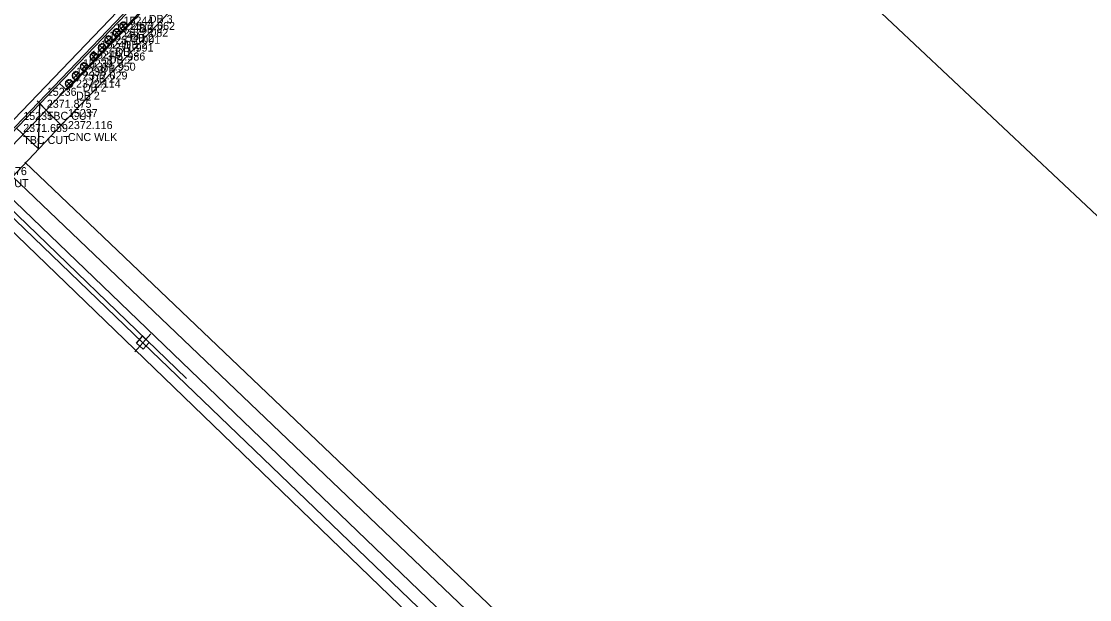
# Model space of a CAD drawing. Extents: x 2377639 to 2379738, y 729875 to 732734.
# Drawn here: x 2378522.8 to 2378789.8, y 730567.8 to 730712.2 of the extents above; entities that cross this region are included whole.
import ezdxf

# ---------------------------------------------------------------- set-up
doc = ezdxf.new("R2010")
doc.units = 0
for name, color, linetype in [('Default', 7, 'Continuous'), ('TOPO_CURBGTR_Back-of-Curb', 7, 'Continuous'), ('TOPO_CURBGTR_Face-of-Curb', 7, 'Continuous'), ('TOPO_CURBGTR_Lip-of-Gutter', 7, 'Continuous'), ('TOPO_DATA_Elevations', 7, 'Continuous'), ('TOPO_ELEC_Cable_Overhead-Exist', 7, 'Continuous'), ('TOPO_ELEC_Power-Pole', 7, 'Continuous'), ('TOPO_GAS_Line', 7, 'Continuous'), ('TOPO_LNDSCP_Tree', 7, 'Continuous'), ('TOPO_SAN_Plastic-Pipe', 7, 'Continuous'), ('TOPO_STORM_Line-Other', 7, 'Continuous'), ('TOPO_SW_Back', 7, 'Continuous'), ('TOPO_TELE_Overhead-Line', 7, 'Continuous'), ('TOPO_TV_Cable-Overhead', 7, 'Continuous'), ('TOPO_WTRUTIL_Line', 7, 'Continuous')]:
    doc.layers.add(name, color=color, linetype=linetype)

# ---------------------------------------------------------------- blocks, each defined once
blk = doc.blocks.new('DB_1')
at = {"layer": 'Default'}
for centre, radius, start, end in [((-0.101, -0.007), 0.0254, 74.3823, 292.6388), ((-0.092, 0.042), 0.0254, 45.5823, 263.8388), ((-0.059, 0.081), 0.0254, 16.7823, 235.0388), ((-0.012, 0.1), 0.0254, 347.9823, 206.2388), ((0, 0), 0.00318, 0, 180), ((0, 0), 0.00318, 180, 0), ((0.038, 0.093), 0.0254, 319.1823, 177.4388), ((0.079, 0.064), 0.0254, 290.3823, 148.6388), ((0.1, 0.018), 0.0254, 261.5823, 119.8388), ((-0.086, -0.056), 0.0254, 103.1823, 321.4388), ((-0.049, -0.09), 0.0254, 131.9823, 278.4601), ((-0.025, -0.1), 0.0254, 218.161, 4.6388), ((0.026, -0.1), 0.0254, 175.1823, 33.4388), ((0.07, -0.076), 0.0254, 203.9823, 62.2388), ((0.097, -0.033), 0.0254, 232.7823, 91.0388)]:
    blk.add_arc(centre, radius, start, end, dxfattribs=at)
blk = doc.blocks.new('UP_1')
at = {"layer": 'Default'}
for p, q in [((0, 0.0381), (0, -0.0381)), ((-0.0145, 0.0145), (0.0145, 0.0145)), ((-0.0145, -0.0145), (-0.0145, 0.0145)), ((0.0145, 0.0145), (0.0145, -0.0145)), ((0.0145, -0.0145), (-0.0145, -0.0145))]:
    blk.add_line(p, q, dxfattribs=at)

msp = doc.modelspace()

# ---------------------------------------------------------------- linework, layer by layer
at = {"layer": 'TOPO_CURBGTR_Back-of-Curb'}
msp.add_lwpolyline([(2378428.64, 730588.82), (2378465.5, 730627.29), (2378502.36, 730665.57), (2378506, 730669.31), (2378527.48, 730691.63), (2378605.98, 730773.58), (2378608.94, 730776.83)], dxfattribs=at)
at = {"layer": 'TOPO_CURBGTR_Face-of-Curb'}
msp.add_lwpolyline([(2378428.28, 730589.17), (2378465.14, 730627.64), (2378502, 730665.92), (2378505.64, 730669.66), (2378527.12, 730691.97), (2378605.61, 730773.92), (2378608.57, 730777.17)], dxfattribs=at)
at = {"layer": 'TOPO_CURBGTR_Lip-of-Gutter'}
msp.add_lwpolyline([(2378609, 730779.64), (2378604.75, 730775.02), (2378431.05, 730594.21), (2378426.07, 730588.91)], dxfattribs=at)
at = {"layer": 'TOPO_DATA_Elevations'}
for p, q in [((2378547.64, 730710.36), (2378549.06, 730711.78)), ((2378547.64, 730711.78), (2378549.06, 730710.36)), ((2378545.97, 730708.69), (2378547.38, 730710.11)), ((2378545.97, 730710.11), (2378547.38, 730708.69)), ((2378542.28, 730704.95), (2378543.7, 730706.37)), ((2378542.28, 730706.37), (2378543.7, 730704.95)), ((2378543.93, 730706.9), (2378545.35, 730708.31)), ((2378543.93, 730708.31), (2378545.35, 730706.9)), ((2378540.23, 730702.73), (2378541.64, 730704.15)), ((2378540.23, 730704.15), (2378541.64, 730702.73)), ((2378537.82, 730700.19), (2378539.23, 730701.61)), ((2378537.82, 730701.61), (2378539.23, 730700.19)), ((2378535.78, 730697.99), (2378537.2, 730699.41)), ((2378535.78, 730699.41), (2378537.2, 730697.99)), ((2378534.06, 730695.97), (2378535.48, 730697.38)), ((2378534.06, 730697.38), (2378535.48, 730695.97)), ((2378526.77, 730690.92), (2378528.19, 730692.34)), ((2378526.77, 730692.34), (2378528.19, 730690.92)), ((2378532.06, 730685.62), (2378533.47, 730687.03)), ((2378532.06, 730687.03), (2378533.47, 730685.62))]:
    msp.add_line(p, q, dxfattribs=at)
at = {"layer": 'TOPO_ELEC_Cable_Overhead-Exist'}
for p, q in [((2378553.19, 730631.94), (2378457.25, 730724.11)), ((2378651.85, 730537.16), (2378553.19, 730631.94))]:
    msp.add_line(p, q, dxfattribs=at)
at = {"layer": 'TOPO_GAS_Line'}
msp.add_line((2378523.71, 730677.02), (2378852.87, 730363.52), dxfattribs=at)
at = {"layer": 'TOPO_SAN_Plastic-Pipe'}
msp.add_line((2378737.85, 730466.14), (2378460.89, 730730.47), dxfattribs=at)
at = {"layer": 'TOPO_STORM_Line-Other'}
for q in [(2378187, 730332.08), (2378188.38, 730333.53)]:
    msp.add_line((2378608.31, 730773.03), q, dxfattribs=at)
at = {"layer": 'TOPO_SW_Back'}
msp.add_line((2378527.48, 730691.63), (2378532.77, 730686.32), dxfattribs=at)
for points in [[(2378532.38, 730696.74), (2378534.18, 730695.01), (2378607.54, 730771.6), (2378605.7, 730773.28)], [(2378474.98, 730627.55), (2378508.09, 730660.21), (2378532.77, 730686.32), (2378606.65, 730763.63), (2378611.23, 730768.23), (2378618.35, 730761.5)], [(2378521.63, 730685.55), (2378527.13, 730680.36), (2378527.48, 730691.63)]]:
    msp.add_lwpolyline(points, dxfattribs=at)
at = {"layer": 'TOPO_TELE_Overhead-Line'}
for p, q in [((2378751.05, 730446.34), (2378268.25, 730910.16)), ((2378564.13, 730622.97), (2378353.69, 730826.29))]:
    msp.add_line(p, q, dxfattribs=at)
at = {"layer": 'TOPO_TV_Cable-Overhead'}
msp.add_line((2378746.7, 730441.54), (2378265.21, 730906.27), dxfattribs=at)
at = {"layer": 'TOPO_WTRUTIL_Line'}
msp.add_line((2378650.11, 730796.86), (2378885.8, 730574.99), dxfattribs=at)

# ---------------------------------------------------------------- block references
at = {"layer": 'TOPO_ELEC_Power-Pole', "xscale": 78.74, "yscale": 78.74000000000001, "rotation": -41.90525780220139}
msp.add_blockref('UP_1', (2378553.19, 730631.94), dxfattribs=at)
at = {"layer": 'TOPO_LNDSCP_Tree', "xscale": 7.8740000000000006, "yscale": 7.8740000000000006}
for p in [(2378548.35, 730711.07), (2378546.68, 730709.4), (2378542.99, 730705.66), (2378544.64, 730707.61), (2378540.94, 730703.44), (2378538.52, 730700.9), (2378536.49, 730698.7), (2378534.77, 730696.67)]:
    msp.add_blockref('DB_1', p, dxfattribs=at)

# ---------------------------------------------------------------- texts
at = {"layer": 'TOPO_DATA_Elevations'}
for s, p in [('15243', (2378546.35, 730709.61)), ('15244', (2378548.38, 730711.4)), ('2372.062', (2378550.06, 730710.07)), ('DB 3', (2378554.69, 730711.83)), ('15242', (2378544.7, 730707.66)), ('2372.082', (2378548.38, 730708.4)), ('DB 2', (2378550.06, 730707.07)), ('DB 2', (2378552.22, 730709.37)), ('15241', (2378542.64, 730705.44)), ('2371.991', (2378544.7, 730704.66)), ('2372.001', (2378546.35, 730706.61)), ('DB 2', (2378548.38, 730705.4)), ('15240', (2378540.23, 730702.9)), ('2371.986', (2378542.64, 730702.44)), ('DB 2', (2378544.7, 730701.66)), ('DB 2', (2378546.35, 730703.61)), ('15239', (2378538.2, 730700.7)), ('2371.950', (2378540.23, 730699.9)), ('DB 2', (2378542.64, 730699.44)), ('15238', (2378536.48, 730698.67)), ('2372.029', (2378538.2, 730697.7)), ('DB 2', (2378540.23, 730696.9)), ('15236', (2378529.19, 730693.63)), ('2372.114', (2378536.48, 730695.67)), ('DB 2', (2378538.2, 730694.7)), ('DB 2', (2378536.48, 730692.67)), ('2371.875', (2378529.19, 730690.63)), ('15237', (2378534.47, 730688.32)), ('15235', (2378523.3, 730687.59)), ('TBC CUT', (2378529.19, 730687.63)), ('2371.659', (2378523.3, 730684.59)), ('2372.116', (2378534.47, 730685.32)), ('TBC CUT', (2378523.3, 730681.59)), ('CNC WLK', (2378534.47, 730682.32)), ('2371.576', (2378513.04, 730673.81)), ('TBC CUT', (2378513.04, 730670.81))]:
    msp.add_text(s, height=2, dxfattribs=at).set_placement(p)

doc.saveas('drawing.dxf')
